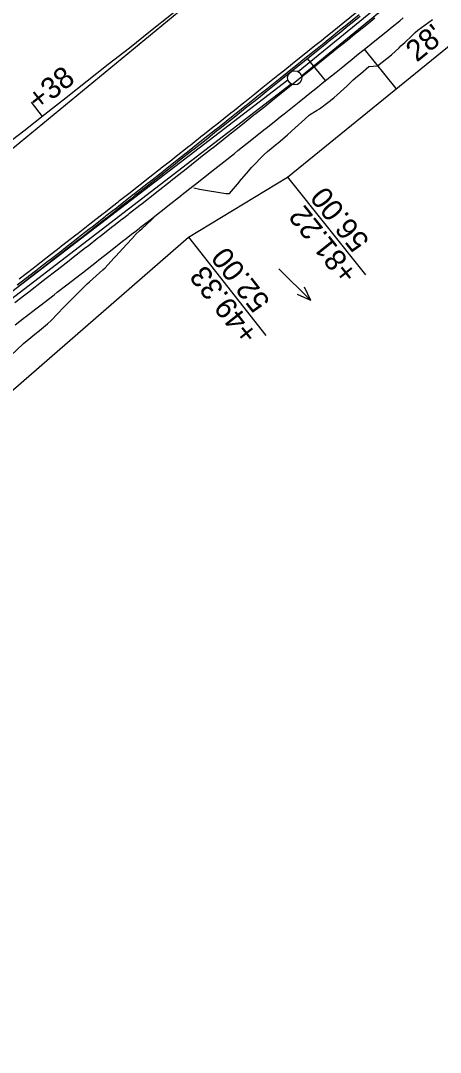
# Model space of a CAD drawing. Extents: x 1147550 to 1149124, y 2017436 to 2018779.
# Drawn here: x 1148565.1 to 1148682.7, y 2017968.7 to 2018257.9 of the extents above; entities that cross this region are included whole.
import ezdxf

# ---------------------------------------------------------------- set-up
doc = ezdxf.new("R2010")
doc.units = 0
for name, color, linetype in [('S_EDGE_CONCRETE', 7, 'Continuous'), ('S_ELECTRIC_UTILITIES', 7, 'Continuous'), ('S_HEADWALL', 7, 'Continuous'), ('S_MAILBOX', 7, 'Continuous'), ('S_SECONDARY_CTL', 7, 'Continuous'), ('S_TANK', 7, 'Continuous'), ('S_TELEPHONE_UTILITIES', 7, 'Continuous'), ('S_TELEPHONE_UTILITIES_ANNOT', 7, 'Continuous')]:
    doc.layers.add(name, color=color, linetype=linetype)

msp = doc.modelspace()

# ---------------------------------------------------------------- linework, layer by layer
at = {"layer": 'S_EDGE_CONCRETE'}
msp.add_line((1148491.47, 2018163.46), (1148677.53, 2018316.54), dxfattribs=at)
msp.add_arc((1145037.29, 2022741.09), 5729.58, 304.629463, 309.445337, dxfattribs=at)
at = {"layer": 'S_ELECTRIC_UTILITIES'}
for points in [[(1148639.91, 2018214.06), (1148661.71, 2018186.67)], [(1148612.18, 2018197.22), (1148633.82, 2018169.71)]]:
    msp.add_lwpolyline(points, dxfattribs=at)
at = {"layer": 'S_HEADWALL'}
for p, q in [((1148670.38, 2018238.87), (1148661.44, 2018249.9)), ((1148650.54, 2018241.12), (1148645.5, 2018247.33)), ((1148568.04, 2018235.03), (1148571.12, 2018231.09))]:
    msp.add_line(p, q, dxfattribs=at)
at = {"layer": 'S_MAILBOX'}
msp.add_lwpolyline([(1147623.68, 2017436.42), (1147751.67, 2017548.43), (1147958.55, 2017704.02), (1148020.45, 2017753.36), (1148124.6, 2017828.73), (1148174.25, 2017853.51), (1148282.74, 2017941.53), (1148421.63, 2018031.39), (1148612.18, 2018197.22), (1148639.91, 2018214.06), (1148753.45, 2018306.48), (1148799.03, 2018350.69)], dxfattribs=at)
at = {"layer": 'S_SECONDARY_CTL'}
for points in [[(1148613.64, 2018211.1), (1148615.25, 2018210.71), (1148622.65, 2018209.48), (1148623.6, 2018209.45), (1148626.44, 2018212.78), (1148626.46, 2018212.79), (1148628.94, 2018215.76), (1148629.76, 2018216.74), (1148633.3, 2018220.39), (1148634.27, 2018221.21), (1148636.93, 2018223.4), (1148637.19, 2018223.6), (1148639.85, 2018225.95), (1148640.96, 2018226.95), (1148642.04, 2018227.92), (1148644.72, 2018230.33), (1148646.07, 2018231.54), (1148648.21, 2018232.85), (1148648.86, 2018233.21), (1148651.55, 2018235.23), (1148652.83, 2018236.33), (1148656.61, 2018239.66), (1148658.29, 2018241.32), (1148659.54, 2018242.35), (1148660.36, 2018243.04), (1148662.64, 2018245.1), (1148665.06, 2018245.25), (1148669.02, 2018248.37), (1148671.14, 2018250.34), (1148671.67, 2018250.83), (1148672.72, 2018251.81), (1148674.74, 2018253.69), (1148675.68, 2018254.56), (1148676.42, 2018255.25), (1148680.5, 2018258.22)], [(1148606.37, 2018206.01), (1148610.19, 2018208.99)], [(1148562.25, 2018163.94), (1148565.93, 2018167.43), (1148566.97, 2018168.28), (1148569.53, 2018170.41), (1148569.81, 2018170.64), (1148572.59, 2018172.96), (1148573.65, 2018173.92), (1148577.2, 2018177.57), (1148578, 2018178.39), (1148580.39, 2018180.82), (1148580.77, 2018181.19), (1148583.75, 2018184.12), (1148584.39, 2018184.75), (1148588.16, 2018188.1), (1148588.77, 2018188.68), (1148591.22, 2018191.32), (1148591.67, 2018191.8), (1148594.88, 2018195.3), (1148595.12, 2018195.56), (1148597.06, 2018197.71), (1148597.18, 2018197.84), (1148598.63, 2018199.24), (1148599.02, 2018199.6), (1148601.77, 2018202.12), (1148602.35, 2018202.66)]]:
    msp.add_lwpolyline(points, dxfattribs=at)
at = {"layer": 'S_TANK'}
for p, q in [((1148637.5, 2018188.36), (1148646.38, 2018179.47)), ((1148646.38, 2018179.47), (1148644.65, 2018183.18)), ((1148646.38, 2018179.47), (1148642.67, 2018181.2))]:
    msp.add_line(p, q, dxfattribs=at)
at = {"layer": 'S_TELEPHONE_UTILITIES'}
for points in [[(1148563.45, 2018178.88), (1148566.31, 2018181.08), (1148567.43, 2018181.95), (1148571.41, 2018185.04), (1148572.3, 2018185.73), (1148574.97, 2018187.8), (1148575.38, 2018188.12), (1148578.66, 2018190.67), (1148579.36, 2018191.21), (1148583.32, 2018194.31), (1148583.98, 2018194.82), (1148586.78, 2018197), (1148587.29, 2018197.4), (1148590.98, 2018200.29), (1148591.25, 2018200.5), (1148593.5, 2018202.26), (1148593.63, 2018202.36), (1148595.22, 2018203.6), (1148595.63, 2018203.93), (1148598.55, 2018206.22), (1148599.17, 2018206.71), (1148603.13, 2018209.82), (1148603.28, 2018209.94), (1148607.08, 2018212.93), (1148607.29, 2018213.1), (1148610.23, 2018215.42), (1148611.03, 2018216.05), (1148614.98, 2018219.17), (1148615.55, 2018219.62), (1148618.91, 2018222.28), (1148618.93, 2018222.3), (1148621.89, 2018224.65), (1148622.87, 2018225.42), (1148626.81, 2018228.55), (1148627.8, 2018229.34), (1148630.49, 2018231.48), (1148630.74, 2018231.69), (1148633.51, 2018233.89), (1148634.68, 2018234.83), (1148635.8, 2018235.72), (1148638.61, 2018237.97), (1148640.02, 2018239.1), (1148641.96, 2018240.65), (1148642.54, 2018241.11), (1148645.15, 2018243.2), (1148646.46, 2018244.26), (1148650.38, 2018247.41), (1148652.21, 2018248.88), (1148653.47, 2018249.89), (1148654.3, 2018250.56), (1148656.68, 2018252.48), (1148658.22, 2018253.72), (1148662.14, 2018256.88), (1148664.38, 2018258.7)], [(1148563.59, 2018172.66), (1148566.22, 2018174.69), (1148566.51, 2018174.92), (1148569.37, 2018177.13), (1148570.49, 2018178), (1148574.47, 2018181.09), (1148575.37, 2018181.78), (1148578.04, 2018183.85), (1148578.45, 2018184.18), (1148581.73, 2018186.72), (1148582.43, 2018187.27), (1148586.4, 2018190.36), (1148587.05, 2018190.87), (1148589.86, 2018193.06), (1148590.37, 2018193.46), (1148594.06, 2018196.35), (1148594.34, 2018196.56), (1148596.58, 2018198.32), (1148596.72, 2018198.43), (1148598.3, 2018199.67), (1148598.72, 2018199.99), (1148601.64, 2018202.29), (1148602.26, 2018202.78), (1148606.22, 2018205.89), (1148606.37, 2018206.01), (1148610.18, 2018209.01), (1148610.39, 2018209.17), (1148613.33, 2018211.49), (1148614.13, 2018212.13), (1148618.08, 2018215.25), (1148618.66, 2018215.7), (1148622.02, 2018218.37), (1148622.03, 2018218.38), (1148625, 2018220.73), (1148625.98, 2018221.51), (1148629.92, 2018224.64), (1148630.91, 2018225.43), (1148633.6, 2018227.57), (1148633.86, 2018227.78), (1148636.63, 2018229.98), (1148637.8, 2018230.92), (1148638.92, 2018231.82), (1148641.73, 2018234.06), (1148643.14, 2018235.19), (1148645.09, 2018236.75), (1148645.66, 2018237.21), (1148648.28, 2018239.3), (1148649.59, 2018240.36), (1148653.52, 2018243.51), (1148655.35, 2018244.98), (1148656.6, 2018246), (1148657.44, 2018246.67), (1148659.82, 2018248.59), (1148661.36, 2018249.83), (1148665.28, 2018253), (1148667.52, 2018254.81), (1148668.08, 2018255.26), (1148669.2, 2018256.16), (1148671.33, 2018257.89), (1148672.33, 2018258.7)], [(1148564.16, 2018183.85), (1148565.29, 2018184.72), (1148569.26, 2018187.8), (1148570.16, 2018188.5), (1148572.82, 2018190.56), (1148573.24, 2018190.89), (1148576.51, 2018193.43), (1148577.21, 2018193.97), (1148581.17, 2018197.07), (1148581.83, 2018197.58), (1148584.63, 2018199.76), (1148585.14, 2018200.16), (1148588.82, 2018203.04), (1148589.1, 2018203.26), (1148591.34, 2018205.01), (1148591.47, 2018205.12), (1148593.06, 2018206.36), (1148593.47, 2018206.68), (1148596.39, 2018208.97), (1148597.01, 2018209.46), (1148600.97, 2018212.57), (1148601.12, 2018212.69), (1148604.92, 2018215.68), (1148605.13, 2018215.85), (1148608.06, 2018218.17), (1148608.86, 2018218.8), (1148612.81, 2018221.92), (1148613.38, 2018222.37), (1148616.74, 2018225.03), (1148616.75, 2018225.04), (1148619.72, 2018227.39), (1148620.69, 2018228.16), (1148624.63, 2018231.29), (1148625.62, 2018232.08), (1148628.3, 2018234.22), (1148628.56, 2018234.43), (1148631.32, 2018236.63), (1148632.49, 2018237.56), (1148633.62, 2018238.46), (1148636.42, 2018240.7), (1148637.83, 2018241.83), (1148639.77, 2018243.38), (1148640.35, 2018243.84), (1148642.96, 2018245.93), (1148644.27, 2018246.99), (1148648.19, 2018250.14), (1148650.02, 2018251.61), (1148651.27, 2018252.62), (1148652.11, 2018253.29), (1148654.49, 2018255.21), (1148656.02, 2018256.45), (1148659.94, 2018259.61)], [(1148564.47, 2018183.46), (1148565.59, 2018184.33), (1148569.57, 2018187.41), (1148570.46, 2018188.1), (1148573.13, 2018190.17), (1148573.54, 2018190.49), (1148576.81, 2018193.04), (1148577.51, 2018193.58), (1148581.48, 2018196.67), (1148582.13, 2018197.18), (1148584.94, 2018199.37), (1148585.44, 2018199.77), (1148589.13, 2018202.65), (1148589.41, 2018202.86), (1148591.65, 2018204.62), (1148591.78, 2018204.72), (1148593.36, 2018205.97), (1148593.78, 2018206.29), (1148596.7, 2018208.58), (1148597.32, 2018209.07), (1148601.27, 2018212.18), (1148601.42, 2018212.3), (1148605.23, 2018215.29), (1148605.44, 2018215.46), (1148608.37, 2018217.77), (1148609.17, 2018218.41), (1148613.12, 2018221.52), (1148613.69, 2018221.98), (1148617.05, 2018224.63), (1148617.06, 2018224.65), (1148620.03, 2018227), (1148621, 2018227.77), (1148624.94, 2018230.9), (1148625.93, 2018231.69), (1148628.62, 2018233.83), (1148628.87, 2018234.03), (1148631.64, 2018236.24), (1148632.81, 2018237.17), (1148633.93, 2018238.07), (1148636.73, 2018240.31), (1148638.14, 2018241.44), (1148640.09, 2018242.99), (1148640.66, 2018243.45), (1148643.27, 2018245.54), (1148644.58, 2018246.6), (1148648.5, 2018249.75), (1148650.33, 2018251.22), (1148651.59, 2018252.23), (1148652.42, 2018252.9), (1148654.8, 2018254.82), (1148656.34, 2018256.06), (1148660.25, 2018259.22)], [(1148564.68, 2018185.51), (1148568.65, 2018188.59), (1148569.54, 2018189.29), (1148572.21, 2018191.35), (1148572.62, 2018191.68), (1148575.89, 2018194.22), (1148576.59, 2018194.76), (1148580.56, 2018197.85), (1148581.21, 2018198.36), (1148584.01, 2018200.55), (1148584.52, 2018200.95), (1148588.21, 2018203.83), (1148588.48, 2018204.04), (1148590.72, 2018205.8), (1148590.86, 2018205.9), (1148592.44, 2018207.15), (1148592.85, 2018207.47), (1148595.77, 2018209.76), (1148596.39, 2018210.25), (1148600.35, 2018213.36), (1148600.5, 2018213.48), (1148604.3, 2018216.47), (1148604.51, 2018216.64), (1148607.44, 2018218.95), (1148608.24, 2018219.58), (1148612.19, 2018222.7), (1148612.76, 2018223.15), (1148616.11, 2018225.81), (1148616.13, 2018225.82), (1148619.1, 2018228.17), (1148620.07, 2018228.95), (1148624.01, 2018232.08), (1148625, 2018232.86), (1148627.68, 2018235), (1148627.94, 2018235.21), (1148630.7, 2018237.41), (1148631.87, 2018238.34), (1148632.99, 2018239.24), (1148635.8, 2018241.48), (1148637.21, 2018242.61), (1148639.15, 2018244.16), (1148639.72, 2018244.62), (1148642.33, 2018246.71), (1148643.65, 2018247.77), (1148647.56, 2018250.92), (1148649.39, 2018252.39), (1148650.65, 2018253.4), (1148651.48, 2018254.07), (1148653.86, 2018255.98), (1148655.4, 2018257.23), (1148659.31, 2018260.38)]]:
    msp.add_lwpolyline(points, dxfattribs=at)
at = {"layer": 'S_TELEPHONE_UTILITIES_ANNOT'}
for p, q in [((1148642.87, 2018243.65), (1148860.75, 2018422.28)), ((1148642.87, 2018243.65), (1148860.75, 2018422.28)), ((1148643.82, 2018242.49), (1148861.7, 2018421.12)), ((1148643.82, 2018242.49), (1148861.7, 2018421.12)), ((1148451.36, 2018096.62), (1148639.98, 2018241.36)), ((1148451.36, 2018096.62), (1148639.98, 2018241.36)), ((1148452.27, 2018095.43), (1148640.9, 2018240.17)), ((1148452.27, 2018095.43), (1148640.9, 2018240.17))]:
    msp.add_line(p, q, dxfattribs=at)
msp.add_circle((1148641.91, 2018241.89), 2, dxfattribs=at)

# ---------------------------------------------------------------- texts
at = {"layer": 'S_ELECTRIC_UTILITIES'}
for s, rotation, p in [('56.00', 128.5128, (1148663.08, 2018196.19)), ('+81.22', 128.5128, (1148659.97, 2018187.24)), ('52.00', 128.1939, (1148635.25, 2018179.22)), ('+49.33', 128.1939, (1148632.1, 2018170.29))]:
    msp.add_text(s, height=6, rotation=rotation, dxfattribs=at).set_placement(p)
at = {"layer": 'S_HEADWALL'}
for s, rotation, p in [("28'", 39.0406, (1148676.12, 2018246.11)), ('+38', 38.0806, (1148570.01, 2018232.51))]:
    msp.add_text(s, height=6, rotation=rotation, dxfattribs=at).set_placement(p)

doc.saveas('drawing.dxf')
